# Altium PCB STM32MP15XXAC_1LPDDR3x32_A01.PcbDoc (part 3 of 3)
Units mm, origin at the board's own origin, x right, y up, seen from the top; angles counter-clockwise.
Board outline 89 x 120 mm, 6 copper layers (Top Layer, Signal Layer 1, Signal Layer 2, Signal Layer 3, Signal Layer 4, Bottom Layer), stack 1.556 mm thick; 93 components, 99 nets, 917 pads, 464 vias.
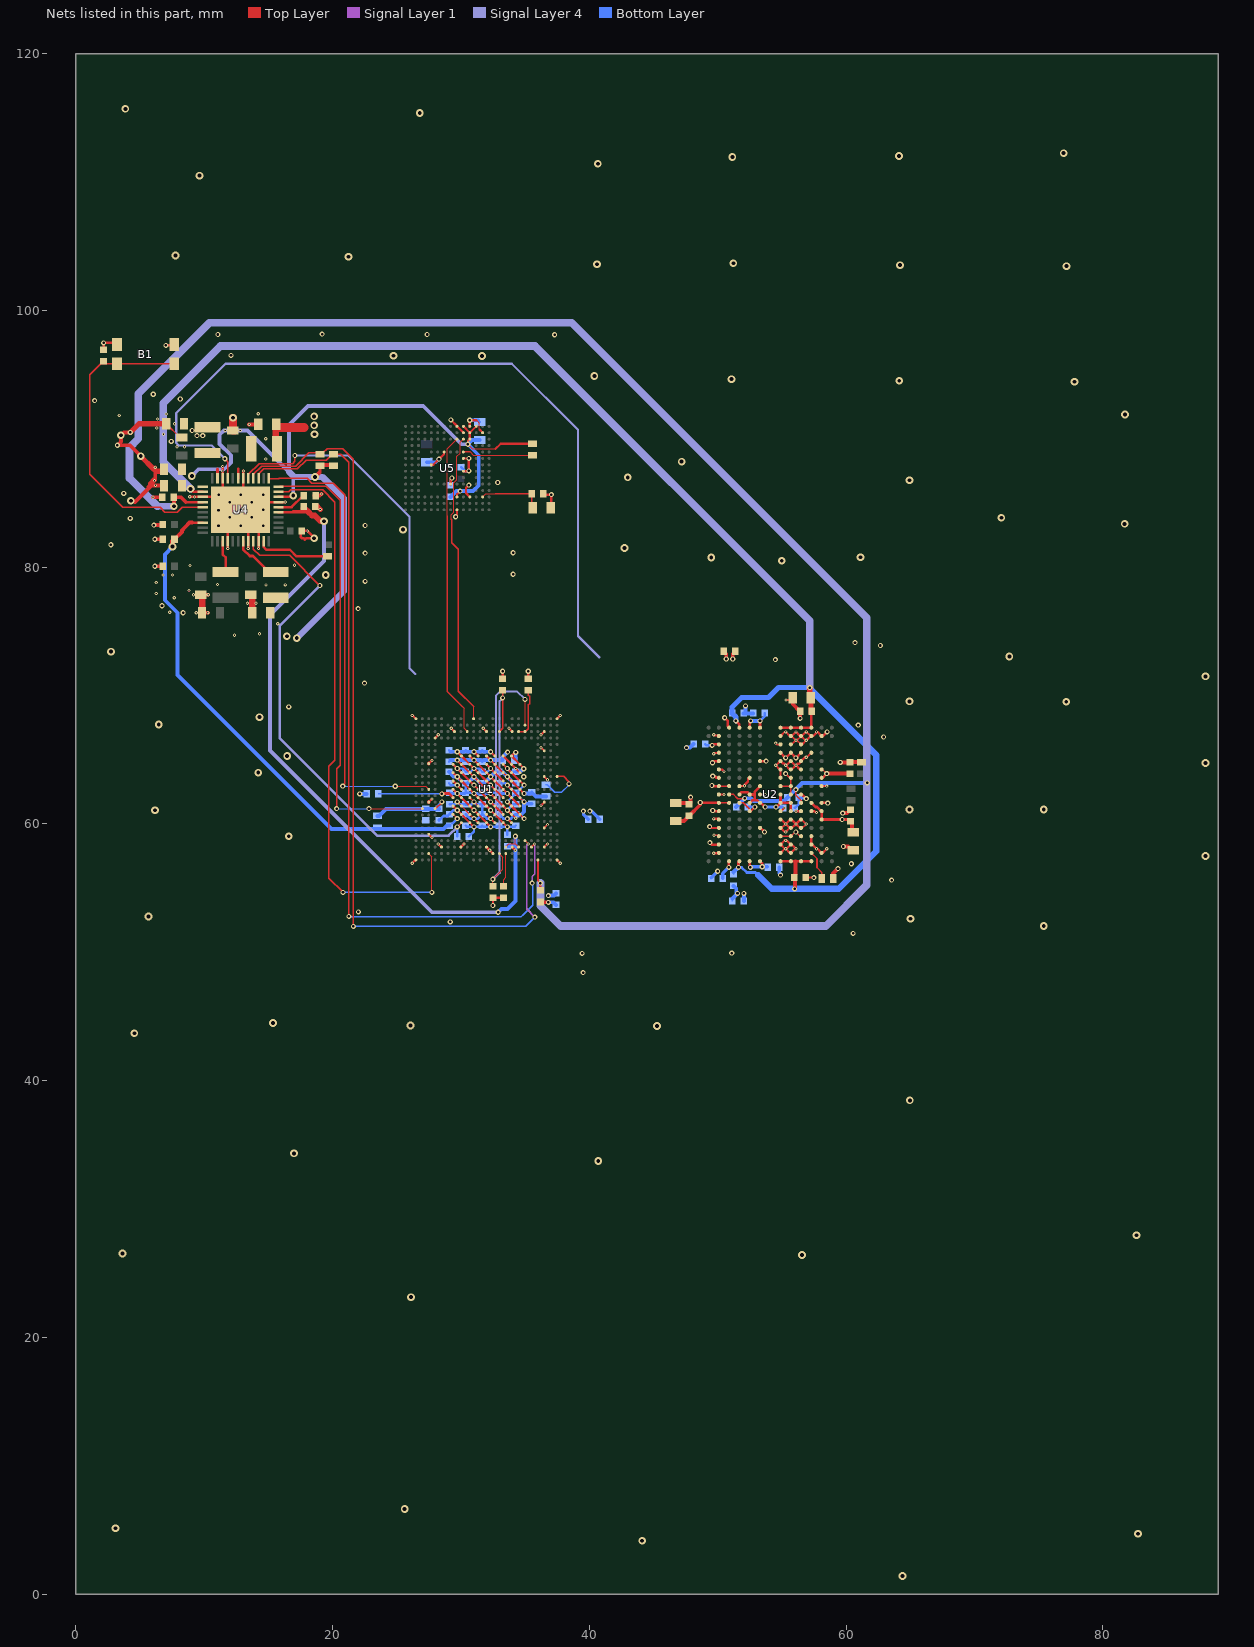
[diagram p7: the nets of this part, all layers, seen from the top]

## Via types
v1: diameter 0.4, hole 0.2, Top Layer to Bottom Layer, tented both sides, 258 vias
v2: diameter 0.25, hole 0.1, Top Layer to Signal Layer 1, tented top, 105 vias
v3: diameter 0.6, hole 0.3, Top Layer to Bottom Layer, tented both sides, 95 vias
v4: diameter 0.25, hole 0.1, Top Layer to Signal Layer 1, tented both sides, 6 vias

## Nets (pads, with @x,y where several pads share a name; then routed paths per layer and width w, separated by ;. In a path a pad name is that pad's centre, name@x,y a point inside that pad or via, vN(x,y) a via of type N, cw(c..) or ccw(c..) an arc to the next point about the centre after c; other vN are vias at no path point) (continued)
GND: B1.1 B1.2 C1.2 C2.2 C3.2 C4.2 C5.2 C6.2 C7.2 C8.2 C9.2 C10.2 C11.2 C12.2 C13.2 C14.1 C15.1 C16.1 C17.2 C18.1 C19.2 C20.2 C21.2 C29.1 C30.1 C31.1 C32.1 C33.1 C34.1 C35.1 C36.1 C37.1 C38.1 C39.1 C40.1 C41.1 C42.1 C43.2 C44.1 C45.1 C46.1 C47.1 C48.1 C49.1 C50.1 C51.1 C52.1 C53.1 C54.1 C55.1 C56.1 C57.1 C58.1 C59.1 C61.1 C66.1 C67.1 C68.1 C69.1 C70.1 C71.1 C75.1 C76.1 C77.1 C78.1 C79.1 C80.1 C81.1 C82.1 C83.1 C84.1 C92.1 C94.1 C95.1 C96.1 C149.2 C150.2 R24.2 R49.1 R65.2 U1.1A3 U1.1A5 U1.1A7 U1.1B2 U1.1B4 U1.1B6 U1.1B8 U1.1C1 U1.1C3 U1.1C5 U1.1C7 U1.1C9 U1.1D2 U1.1D4 U1.1D6 U1.1D8 U1.1E1 U1.1E3 U1.1E5 U1.1E7 U1.1E9 U1.1F2 U1.1F4 U1.1F6 U1.1F8 U1.1G1 U1.1G3 U1.1G5 U1.1G7 U1.1G9 U1.1H2 U1.1H4 U1.1H6 U1.1H8 U1.1J3 U1.1J5 U1.1J7 U1.A1 U1.A23 U1.AA5 U1.AA8 U1.AA12 U1.AA16 U1.AA21 U1.AB13 U1.AC1 U1.AC23 U1.C7 U1.C12 U1.C16 U1.C21 U1.D4 U1.F21 U1.H3 U1.K21 U1.P3 U1.P21 U1.V21 U1.W3 U2.B2 U2.B5 U2.B6 U2.B12 U2.C3 U2.C5 U2.C6 U2.D3 U2.D12 U2.E4 U2.E5 U2.E6 U2.F4 U2.F5 U2.F6 U2.F12 U2.G3 U2.G4 U2.G6 U2.G9 U2.H2 U2.H10 U2.J4 U2.J8 U2.J12 U2.K2 U2.K10 U2.L6 U2.L9 U2.M4 U2.M5 U2.M6 U2.M12 U2.N4 U2.N5 U2.N6 U2.P3 U2.P12 U2.R4 U2.R5 U2.R6 U2.T2 U2.T3 U2.T4 U2.T5 U2.T6 U2.T12 U4.6 U4.10 U4.15 U4.26 U4.30 U4.32 U4.41 U4.ep U5.A6 U5.C4 U5.E7 U5.G5 U5.H10 U5.J5 U5.K8 U5.N2 U5.N5 U5.P4 U5.P6 | length 192.9
  Top Layer w0.09: 31.225,91.45 31.45,91.225 31.45,90.725
  Top Layer w0.1: U2.H10@51.7,61.65 52.009,61.65 52.5,61.159 U2.G9@52.5,61 ; U2.E4@56.5,59.7 56.6,59.7 v2@56.86,59.96 ; U2.F4@56.5,60.35 56.55,60.35 v2(56.9,60)
  Top Layer w0.12: U1.AA21@36.5,58.2 36.504,58.2 U1.AA21@36.545,58.2 ; U1.C21@36.5,67.185 U1.C21@36.5,67.2
  Top Layer w0.127: C29.1@7.05,91.175 8.125,90.1 C18.1@8.25,90.1
  Top Layer w0.15: v2(36.25,65.945) 36.498,65.698 U1.F21@36.5,65.696 ; U1.AA21@36.5,58.196 36.502,58.198 36.504,58.2 v2@36.75,58.446 ; U1.V21@36.5,59.696 36.502,59.698 v2@36.75,59.946 ; U1.K21@36.5,63.696 v2@36.735,63.461 ; C7.2@47.675,61.625 C7.2@47.775,61.525 C7.2@47.9,61.65 ; v2(49.7,65.475) 49.75,65.525 50.1,65.525 U2.P12@50.1,65.55 ; v2(49.725,59.125) 50.025,59.125 U2.D12@50.1,59.05 ; v2(54.525,66.3) 54.65,66.175 54.875,66.175 U2.R6@54.9,66.2 ; U2.R5@55.7,66.2 55.775,66.2 v2(56.1,66.525) ; U2.T5@55.7,66.85 55.775,66.85 v2(56.1,66.525) ; U2.R4@56.5,66.2 v2@56.175,66.525 ; U2.T4@56.5,66.85 v2@56.175,66.525 ; v2(56.1,66.525) v2@56.175,66.525
  Top Layer w0.175: v2(26.225,56.95) 26.475,57.2 U1.AC1@26.5,57.2 ; v2(26.225,68.45) 26.25,68.45 U1.A1@26.5,68.2 ; U1.W3@27.5,59.2 v2(27.75,58.95) ; U1.P3@27.5,61.7 v2(27.75,61.95) ; U5.H10@27.7,87.975 27.85,87.975 v1(28.3,88.425) 28.7,88.825 U5.K8@28.7,88.975 ; U1.D4@28,66.7 v2(28.25,66.95) ; v2(28.25,58.45) U1.AA5@28.5,58.2 ; v1(29.225,91.475) 29.7,91 U5.P6@29.7,90.975 U5.N5@30.2,90.475 ; v2(29.25,67.45) U1.C7@29.5,67.2 ; U1.1G1@29.4,61.4 v1(29.725,61.075) U1.1H2@30.05,60.75 U1.1J3@30.7,60.1 v1(31.025,59.775) ; U1.1E1@29.4,62.7 v1(29.725,62.375) U1.1F2@30.05,62.05 U1.1G3@30.7,61.4 v1(31.025,61.075) U1.1H4@31.35,60.75 U1.1J5@32,60.1 v1(32.325,59.775) ; U1.1C1@29.4,64 v1(29.725,63.675) U1.1D2@30.05,63.35 U1.1E3@30.7,62.7 v1(31.025,62.375) U1.1F4@31.35,62.05 U1.1G5@32,61.4 v1(32.325,61.075) U1.1H6@32.65,60.75 U1.1J7@33.3,60.1 v1(33.625,59.775) ; v1(29.6,83.925) 29.7,84.025 U5.A6@29.7,84.475 ; v1(29.725,64.975) U1.1B2@30.05,64.65 U1.1C3@30.7,64 v1(31.025,63.675) U1.1D4@31.35,63.35 U1.1E5@32,62.7 v1(32.325,62.375) U1.1F6@32.65,62.05 U1.1G7@33.3,61.4 v1(33.625,61.075) U1.1H8@33.95,60.75 33.975,60.75 v2(34.275,60.45) ; U5.G5@30.2,87.475 30.601,87.475 v1(30.625,87.5) v1(30.625,88.475) U5.J5@30.2,88.475 ; v1(30.625,86.4) 30.4,86.175 30.4,85.775 U5.C4@30.7,85.475 ; U1.1A3@30.7,65.3 v1(31.025,64.975) U1.1B4@31.35,64.65 U1.1C5@32,64 v1(32.325,63.675) U1.1D6@32.65,63.35 U1.1E7@33.3,62.7 v1(33.625,62.375) U1.1F8@33.95,62.05 U1.1G9@34.6,61.4 ; U5.P4@30.7,90.948 U5.P4@30.7,90.975 v1(30.7,91.45) 31.225,91.45 ; 31.45,90.725 U5.N2@31.7,90.475 ; v2(31.75,67.45) U1.C12@32,67.2 ; U1.1A5@32,65.3 v1(32.325,64.975) U1.1B6@32.65,64.65 U1.1C7@33.3,64 v1(33.625,63.675) U1.1D8@33.95,63.35 U1.1E9@34.6,62.7 v1(34.925,62.375) ; v1(32.5,53.65) C67.1@32.5,54.25 C69.1@33.325,54.25 ; U1.1A7@33.3,65.3 U1.1B8@33.95,64.65 v2(34.275,64.325) U1.1C9@34.6,64 ; v2(33.75,67.45) U1.C16@34,67.2 ; U1.1C9@34.6,63.975 U1.1C9@34.6,64 ; U1.1C9@34.625,64 U1.1C9@34.6,64 ; v2(36.25,61.45) U1.P21@36.5,61.7 ; v2(36.25,66.95) U1.C21@36.5,67.2 ; C82.1@36.425,85.725 36.5,85.65 v1(37.05,85.65) 37.05,84.675 C83.1@37,84.625 ; U1.AC23@37.5,57.2 v2(37.75,56.95) ; U1.A23@37.5,68.2 v2(37.75,68.45) ; v2(49.7,57.725) 50.075,57.725 U2.B12@50.1,57.75 ; v2(49.7,60.4) 50.05,60.4 U2.F12@50.075,60.375 ; v2(49.7,66.95) 49.766,66.884 50.066,66.884 U2.T12@50.1,66.85 ; U2.J12@50.1,62.3 v4(50.5,62.3) ; U2.M12@50.1,64.25 50.35,64.25 v2(50.5,64.1) ; U2.K10@51.7,62.95 52.075,62.95 v2(52.1,62.975) 52.1,63.041 52.373,63.314 52.373,63.525 52.447,63.6 U2.L9@52.5,63.6 ; U2.G9@52.5,61 52.575,61 v1(52.9,61.325) ; U2.J8@53.3,62.3 v2(53.7,62.3) ; U2.E6@54.825,59.7 U2.E6@54.9,59.7 ; U2.B6@54.9,57.75 v2@55.225,58.075 ; U2.F6@54.9,60.35 54.95,60.35 v2(55.3,60) ; U2.G6@54.9,61.025 U2.G6@54.9,61 54.95,61 v2(55.2,61.25) ; U2.L6@54.9,63.6 U2.M6@54.9,64.25 54.85,64.25 v2(54.525,64.575) 54.575,64.575 U2.N6@54.9,64.9 54.911,64.9 55.098,64.713 55.163,64.713 v2(55.3,64.575) 55.625,64.25 U2.M5@55.7,64.25 55.775,64.25 v2(56.1,64.575) ; U2.T6@54.9,66.85 55.225,67.175 v2(55.3,67.175) 55.625,66.85 U2.T5@55.7,66.85 ; v2(55.325,69.65) 55.85,69.65 C16.1@55.875,69.675 ; v2@55.375,64.575 U2.N5@55.7,64.9 56.025,64.575 v2(56.1,64.575) ; U2.T5@55.775,66.85 v2(56.1,67.175) 56.425,66.85 U2.T4@56.5,66.85 ; v2(56.1,61) U2.G4@56.5,61 ; U2.E4@56.5,59.7 56.4,59.7 v2(56.1,60) ; U2.F4@56.5,60.35 56.45,60.35 v2(56.1,60) ; U2.J4@56.5,62.3 56.575,62.3 v1(56.9,61.975) ; U2.M4@56.5,64.25 56.425,64.25 v2(56.1,64.575) ; U2.N4@56.5,64.9 56.8,65.2 v2(56.9,65.2) 56.95,65.2 U2.P3@57.3,65.55 ; U2.R4@56.5,66.2 U2.R4@56.575,66.2 ; U2.N4@56.52,64.88 56.339,64.7 56.225,64.7 v2(56.1,64.575) ; U2.R4@56.6,66.2 U2.R4@56.575,66.2 ; C3.2@56.875,55.825 v1(57.5,55.825) ; U2.D3@57.3,59.05 U2.C3@57.3,58.4 57.375,58.4 v2(57.7,58.075) 57.775,58.075 U2.B2@58.1,57.75 58.175,57.75 v2(58.5,58.075) ; U2.G3@57.3,61 57.543,61 57.606,60.938 57.663,60.938 v2(57.7,60.9) ; v2(57.7,67.175) v2@57.775,67.175 ; U2.H2@58.1,61.65 v1@58.575,61.65 ; U2.K2@58.1,62.95 v2(58.5,62.95) ; v1(58.525,67.175) 58.2,66.85 U2.T2@58.1,66.85 v2@57.775,67.175 ; C6.2@60.1,64.8 60.125,64.825 C6.2@60.3,64.825 ; C5.2@60.25,61.075 C5.2@60.275,61.1 ; U2.E6@54.9,59.7 55.225,59.375 v2(55.3,59.375) U2.E5@55.625,59.7 ; U2.E6@54.9,59.7 55,59.7 v2(55.3,60) ; v2@55.225,58.075 v2(55.3,58.075) ; v2@55.225,58.075 U2.C6@54.9,58.4 55.225,58.725 v2(55.3,58.725) 55.375,58.725 U2.C5@55.7,58.4 ; v2(55.3,58.075) 55.375,58.075 U2.C5@55.7,58.4 ; v2(55.3,58.075) 55.625,57.75 U2.B5@55.7,57.75 56.025,58.075 v2(56.1,58.075) 55.775,58.4 U2.C5@55.7,58.4 ; v2(55.3,60) 55.65,60.35 U2.F5@55.7,60.35 55.75,60.35 v2(56.1,60) ; v2(55.3,60) 55.6,59.7 U2.E5@55.625,59.7 ; U2.E5@55.625,59.7 U2.E5@55.7,59.7 55.8,59.7 v2(56.1,60) ; U2.T4@56.5,66.85 56.55,66.85 56.888,67.188 56.9,67.2 56.912,67.188 U2.T3@57.25,66.85 ; U2.T4@56.5,66.85 v2@56.825,66.525 ; U2.R4@56.575,66.2 v2@56.862,66.488 ; v2@56.825,66.525 v2@56.862,66.488 ; v2@56.825,66.525 v2(56.9,66.525) v2@56.862,66.488 ; v2@56.862,66.488 56.875,66.475 56.913,66.513 U2.T3@57.25,66.85 ; U2.T3@57.25,66.85 U2.T3@57.3,66.85 57.45,66.85 57.737,67.138 v2@57.775,67.175
  Top Layer w0.2: C44.1@2.175,96.95 v1(2.175,97.475) 3.1,97.475 B1.1@3.225,97.35 ; v1(7.025,97.275) 7.6,97.275 B1.2@7.675,97.35 ; v4(8.882,85.482) 9.243,85.482 v4(9.25,85.475) U4.15@9.9,85.475 10.875,85.475 U4.ep@10.9,85.45 ; v2@11.45,87.825 v2(11.45,87.5) U4.10@11.45,86.925 11.45,85.875 12.125,85.2 v1(12.85,84.475) ; v2(11.85,81.45) U4.26@11.85,82.025 11.85,83.475 12.125,83.75 v1(12.85,84.475) ; v3(12.255,91.64) v3@12.381,91.514 ; v2@13.05,87.5 U4.6@13.05,86.925 13.05,85.65 U4.ep@13.05,84.675 ; v2@13.45,81.425 v2(13.45,81.45) U4.30@13.45,82.025 U4.ep@13.45,83.875 ; v2(14.25,81.45) U4.32@14.25,82.025 14.25,83.075 13.587,83.738 U4.ep@13.45,83.875 ; v2(16.325,85.075) U4.41@15.8,85.075 v1(13.725,85.075) 13.45,85.075 U4.ep@13.05,84.675 ; C51.1@17.537,82.762 17.537,82.338 17.625,82.25 17.757,82.25 17.857,82.15 17.957,82.25 v3(18.575,82.25) ; C51.1@17.6,82.825 v2(18.05,82.825) v3@18.6,82.275 ; U1.H3@27.5,64.7 v2(27.75,64.95) ; U5.E7@29.2,86.475 29.2,86.825 29.312,86.937 v1@29.325,86.95 ; U1.AA8@30,58.2 v2(30.25,58.45) ; U1.AA12@32,58.2 v2(32.25,57.95) U1.AB13@32.5,57.7 ; C66.1@33.25,71.3 v1(33.25,71.9) ; U1.AA16@34,58.2 v2(34.25,57.95) ; C68.1@35.25,71.3 v1(35.25,71.9) ; v1(12.85,84.475) U4.ep@13.45,83.875 ; v1(12.85,84.475) U4.ep@13.05,84.675
  Top Layer w0.3: v1(4.25,90.5) 3.75,90.5 v3(3.525,90.275) 3.525,89.775 v1(3.25,89.5) 4.225,89.5 v3(5.075,88.65) ; v3(4.3,85.175) 4.525,85.175 4.625,85.075 5.675,86.125 ; v2(6.025,85.45) C84.1@6.75,85.45 ; v1(6.1,83.275) 6.75,83.275 C41.1@6.8,83.325 C41.1@6.775,83.35 ; v2(6.144,86.744) 5.925,86.525 5.925,86.5 ; v1(6.175,80.075) C32.1@6.8,80.075 ; v1(6.175,82.175) C49.1@6.8,82.175 ; v2(6.2,87.775) 6.2,87.525 6.2,86.95 ; C46.1@6.85,86.375 v2(6.214,86.375) 5.925,86.375 ; C39.1@9.75,77.85 v2(10.325,77.85) ; C40.1@9.85,76.45 v2(10.3,76.45) ; C33.1@12.255,90.701 12.25,90.696 12.227,90.673 C33.1@12.25,90.65 C33.1@12.4,90.5 ; v2@13.5,91.125 v2(13.525,91.125) 13.95,91.125 14.075,91 C34.1@14.2,90.875 ; C43.2@18.6,85.575 18.649,85.526 C43.2@18.65,85.525 ; C43.2@18.684,85.562 19.012,85.562 v2(19.15,85.7) ; C17.2@36.2,53.925 36.225,53.9 v1(36.825,53.9) ; C15.1@46.75,61.625 C7.2@47.675,61.625 ; C7.2@47.9,61.65 v1(47.9,62.1) ; v1(51.175,72.85) 51.175,73.25 C19.2@51.375,73.45 ; C16.1@55.85,69.825 55.85,69.65 55.85,69.35 C1.2@56.425,68.775 v1(56.425,68.225) ; R65.2@59,55.75 59,56.15 v1(59.375,56.525) ; v1(59.55,64.8) C6.2@60.1,64.8 ; v1(59.75,60.85) 60.1,60.85 C5.2@60.35,61.1 ; v1(59.8,58.25) 60.175,58.25 C14.1@60.475,57.95 ; C6.2@60.3,64.825 R49.1@61.025,64.825 ; 5.675,86.125 5.925,86.375 ; 5.675,86.125 5.675,86.25 5.863,86.438 ; 5.863,86.438 5.775,86.525 6.069,86.819 6.2,86.95 ; 5.863,86.438 5.925,86.375 ; 5.863,86.438 5.925,86.5 ; 5.925,86.375 5.925,86.5 ; 5.925,86.5 6.157,86.732 6.2,86.775 6.2,86.95
  Top Layer w0.4: v1(4.25,90.5) 4.925,91.175 6.325,91.175 C29.1@7.05,91.175 ; v3(5.075,88.65) 6.075,87.65 6.2,87.525 6.25,87.475 C42.1@6.6,87.475 ; C52.1@18.751,84.801 v2(19.053,84.5)
  Top Layer w0.5: C39.1@9.75,77.85 9.85,77.75 C40.1@9.85,76.45 ; C31.1@13.625,77.85 13.625,77.75 13.75,77.625 13.75,77.2 C38.1@13.75,76.45
  Top Layer w0.6: C33.1@12.25,90.65 12.25,90.696 12.25,91.635 v3(12.255,91.64)
  Bottom Layer w0.1: C13.2@51.15,54 C13.2@51.15,54.2
  Bottom Layer w0.15: C9.2@49.5,55.75 C9.2@49.5,55.825
  Bottom Layer w0.175: C35.1@29.075,64.85 C35.1@29.2,64.975 ; C37.1@30.225,63.175 C37.1@30.375,63.175 C37.1@30.525,63.175 ; C96.1@30.375,59.875 C96.1@30.475,59.775 ; C47.1@30.625,59.025 31.025,59.425 v1(31.025,59.775) ; C81.1@31.325,91.45 C81.1@31.475,91.3 ; C36.1@31.525,63.175 C36.1@31.675,63.175 C36.1@31.825,63.175 ; C76.1@31.55,64.975 C76.1@31.675,64.85 C76.1@31.8,64.975 ; C95.1@31.575,59.775 C95.1@31.675,59.875 C95.1@31.775,59.775 ; C45.1@32.725,64.075 C45.1@32.975,64.075 C45.1@33.225,64.075 ; C55.1@32.875,59.775 C55.1@32.975,59.875 C55.1@33.075,59.775 ; C53.1@33.25,65.2 33.25,64.975 C53.1@33.275,64.95 ; C57.1@34.125,63.175 C57.1@34.275,63.175 ; C54.1@34.175,59.775 C54.1@34.275,59.875 ; C59.1@35.4,62.375 35.512,62.488 C59.1@35.525,62.5 ; C4.2@52.025,68.6 52.05,68.625 C4.2@52.175,68.75 ; v1@56.85,62.025 v1(56.9,61.975)
  Bottom Layer w0.2: C58.1@28.3,60.35 C58.1@28.3,60.275 28.65,60.625 28.975,60.625 C70.1@29.125,60.775 29.425,61.075 v1(29.725,61.075) ; C94.1@29.125,62.425 29.175,62.375 v1(29.725,62.375) 30.325,62.375 C48.1@30.375,62.425 ; C80.1@29.2,86.375 29.2,86.825 29.312,86.937 v1@29.325,86.95 ; C78.1@30.025,87.8 30.35,87.475 30.6,87.475 v1(30.625,87.5) ; C37.1@30.375,63.175 C48.1@30.375,62.425 ; C96.1@30.475,59.775 v1(31.025,59.775) C95.1@31.575,59.775 ; C92.1@31.675,62.425 C92.1@31.725,62.375 ; C95.1@31.775,59.775 v1(32.325,59.775) C55.1@32.875,59.775 ; C55.1@33.075,59.775 v1(33.625,59.775) ; C71.1@33.625,59.175 v1(33.625,59.775) ; v1(33.625,61.075) 34.075,61.525 C56.1@34.275,61.525 ; v1(33.625,62.375) 33.025,62.375 C77.1@32.975,62.425 32.375,62.425 v1(32.325,62.375) C92.1@31.725,62.375 ; C54.1@34.175,59.775 v1(33.625,59.775) ; C150.2@52.325,61.325 C150.2@52.35,61.325 v1(52.9,61.325) ; C8.2@56.025,61.25 56.325,61.55 56.325,62.025 v1@56.85,62.025 ; C48.1@30.375,62.425 30.975,62.425 v1(31.025,62.375) 31.675,62.375 C92.1@31.725,62.375
  Bottom Layer w0.25: v1(39.55,61) 39.55,60.75 C21.2@39.925,60.375 ; C9.2@49.5,55.825 v1(50,56.325)
  Bottom Layer w0.3: v1(22.125,62.35) C61.1@22.675,62.35 ; C79.1@27.35,88.175 28.05,88.175 v1(28.3,88.425) ; C75.1@29.075,64.075 29.475,63.675 v1(29.725,63.675) C37.1@30.225,63.175 ; C35.1@29.2,64.975 v1(29.725,64.975) 30.375,64.975 v1(31.025,64.975) C76.1@31.55,64.975 ; C37.1@30.525,63.175 v1(31.025,63.675) C36.1@31.525,63.175 ; v1(30.7,91.45) C81.1@31.325,91.45 ; C76.1@31.8,64.975 v1(32.325,64.975) C53.1@33.25,64.975 ; C36.1@31.825,63.175 v1(32.325,63.675) C45.1@32.725,64.075 ; C45.1@33.225,64.075 v1(33.625,63.675) C57.1@34.125,63.175 ; C53.1@33.25,65.2 v1(33.65,65.6) ; v1(34.925,62.375) 35.4,62.375 35.425,62.375 C59.1@35.525,62.475 35.85,62.15 R24.2@36.625,62.15 ; v1(36.825,53.9) 37.225,53.9 C20.2@37.425,53.7 ; v1(47.575,65.95) 47.85,65.95 C12.2@48.125,66.225 ; C13.2@51.15,54.2 v1(51.55,54.6) ; C2.2@51.25,55.175 51.45,54.975 v1@51.45,54.6 ; C4.2@52.025,68.6 C10.2@52.775,68.6 ; C4.2@52.175,68.75 v1(52.175,69.2) ; C11.2@54.8,56.625 54.8,56.184 v1@54.93,56.055
  other v1: 39.525,48.425 39.45,49.925 51.1,49.95 60.55,51.485 29.175,52.375 22.025,53.15 63.55,55.625 54.9,56.025 60.425,56.9 58.575,61.625 34.9,63.675 62.925,66.775 60.95,67.7 16.6,69.125 22.5,70.975 54.5,72.8 62.675,73.9 60.7,74.125 8.375,76.45 22,76.775 6.725,77 22.55,78.9 34.075,79.45 22.55,81.1 34.075,81.125 2.75,81.75 11.125,83.225 12.875,83.225 14.6,83.225 22.55,83.25 4.25,83.801 12,83.875 13.725,83.875 11.125,84.45 14.6,84.475 12,85.075 11.15,85.65 12.875,85.65 14.6,85.65 3.75,85.75 32.875,86.6 29.3,86.95 7.45,89.8 1.475,92.975 8.15,93.1 6.05,93.475 12.1,96.5 37.3,98.1 11.075,98.125 27.375,98.125 19.2,98.15
  other v2: 36.75,58.45 36.75,59.95 36.75,63.45 56.9,67.175 12.375,74.7 14.325,74.825 15.75,75.6 9.4,76.45 13.375,77.2 14.05,77.2 7.675,77.625 9.175,77.85 8.825,78.175 14.825,78.625 16.325,78.625 11.05,78.65 6.8,79.4 7.55,79.4 8.911,80.125 17.05,80.15 13.075,87.5 11.45,87.85 14.8,88.425 7.9,89.375 8.475,89.375 14.8,90 6.85,90.35 11.65,90.65 12.825,90.65 6.325,90.85 7.7,91.175 6.375,91.55 3.4,91.825 7.05,91.925 14.225,91.95
  other v3: 64.4,1.425 44.125,4.175 82.75,4.725 3.1,5.15 25.625,6.65 26.125,23.15 56.575,26.425 3.65,26.55 82.625,27.975 40.7,33.75 17,34.35 64.975,38.475 4.575,43.7 45.275,44.275 26.075,44.3 15.375,44.5 75.4,52.05 65.025,52.625 5.675,52.8 88,57.5 16.6,59.05 6.175,61.075 64.95,61.125 75.4,61.125 14.225,64 88,64.75 16.475,65.3 6.475,67.75 14.325,68.325 77.15,69.525 64.95,69.55 88,71.5 72.725,73.05 2.75,73.425 19.475,79.4 55,80.5 49.5,80.75 61.125,80.775 42.75,81.5 25.5,82.925 81.7,83.375 72.1,83.85 64.95,86.775 43,87 47.2,88.225 81.725,91.9 77.8,94.45 64.15,94.525 51.075,94.65 40.4,94.9 31.65,96.45 24.75,96.475 77.175,103.45 64.2,103.525 40.6,103.6 51.225,103.675 21.25,104.175 7.775,104.275 9.65,110.5 40.675,111.425 51.15,111.95 64.125,112.025 76.95,112.25 26.8,115.375 3.875,115.7
  other v4: 7.325,76.5 6.275,77.95 6.275,78.8
I2C4_SCL: R37.2 U1.Y18 U4.4 | length 66.5
  Top Layer w0.09: U1.Y18@35,58.7 v2(35.25,58.45)
  Top Layer w0.1: U4.4@13.85,86.925 13.85,87.237 14.488,87.875 17.125,87.875 18.15,88.9 19.025,88.9 19.26,88.9 19.6,89.24 20.81,89.24 21.638,88.413 v1(21.638,52.025)
  Signal Layer 1 w0.1: v2(35.25,58.45) 35.14,58.34 35.14,53.385 v1(35.775,52.75)
  Bottom Layer w0.1: v1(21.638,52.025) 35.05,52.025 v1(35.775,52.75)
I2C4_SDA: R38.2 U1.AA19 U4.3 | length 63.6
  Top Layer w0.1: U4.3@14.25,86.925 14.25,87.267 14.658,87.675 17.275,87.675 17.95,88.35 19.525,88.35 20.012,88.838 R38.2@19.975,88.875 ; R38.2@20.074,88.813 20.637,88.813 21.288,88.162 v1(21.288,52.8) ; U1.AA19@35.5,58.2 v2(35.75,58.45)
  Signal Layer 1 w0.12: v1(35.55,55.4) 35.55,55.9 35.75,56.1 v2(35.75,58.45)
  Bottom Layer w0.1: 34.813,52.888 35.525,53.6 ; v1(35.55,55.4) 35.6,55.35 35.6,54.225
  Bottom Layer w0.12: v1(21.288,52.8) 21.323,52.765 34.69,52.765 34.813,52.888 ; 35.525,53.6 35.6,53.675 35.6,54.225
NetB1_3: B1.3 B1.4 C44.2 U4.17 | length 24.9
  Top Layer w0.1: B1.4@7.675,95.85 B1.3@3.225,95.85 2.175,95.85 1.95,95.85 1.1,95 1.1,87.25 3.675,84.675 6.575,84.675 6.95,84.3 7.925,84.3 8.3,84.675 U4.17@9.9,84.675
NetC43_1: C43.1 U4.40 | length 2.2
  Top Layer w0.2: U4.40@15.8,84.675 16.828,84.675 C43.1@17.689,85.536
NetC61_2: C61.2 U1.1F1 | length 6
  Top Layer w0.2: v1@28.55,62.375 29.075,62.375 U1.1F1@29.4,62.05
  Top Layer w0.3: v1@28.475,62.35 v1(28.525,62.35) v1@28.55,62.375
  Bottom Layer w0.1: C61.2@23.575,62.35 v1(28.525,62.35)
NetC68_2: C68.2 U1.C17 U1.C18 | length 3.9
  Top Layer w0.1: U1.C17@34.5,67.2 U1.C18@35,67.2 35.025,67.2 35.25,67.425 35.25,69.275 35.35,69.375 35.35,69.945 35.25,70.045 C68.2@35.25,70.4
NetC69_2: C69.2 U1.AB15 | length 2.6
  Top Layer w0.09: C69.2@33.325,55.15 33.325,55.675 33.5,55.85 U1.AB15@33.5,57.7
NetC82_2: C82.2 C83.2 U5.C2 | length 5.1
  Top Layer w0.09: U5.C2@31.7,85.475 31.95,85.725 32.7,85.725
  Top Layer w0.1: 32.7,85.725 C82.2@35.525,85.725 35.525,84.7 C83.2@35.6,84.625
NetL1_1: L1.1 U4.7 | length 0.7
  Top Layer w0.2: U4.7@12.65,86.925 12.65,87.672
NetL2_1: L2.1 U4.11 | length 0.7
  Top Layer w0.2: U4.11@11.05,86.925 11.05,87.65
NetL3_1: L3.1 U4.29 | length 3.9
  Top Layer w0.2: U4.29@13.05,82.025 13.05,81.39 13.565,80.875 13.8,80.875 15.05,79.625 L3.1@15.575,79.625
NetL4_1: L4.1 U4.25 | length 2.4
  Top Layer w0.2: U4.25@11.45,82.025 11.45,81 11.675,80.775 L4.1@11.675,79.725
NetR24_1: R24.1 U1.K23 | length 3.6
  Top Layer w0.1: U1.K23@37.5,63.7 38.025,63.7 38.425,63.3 v1(38.425,63.125)
  Bottom Layer w0.12: R24.1@36.625,63.05 36.725,63.05 37.31,62.465 37.849,62.465 38.425,63.041 v1(38.425,63.125)
NetR40_1: R40.1 U5.K5 | length 5.5
  Top Layer w0.09: 30.725,88.975 30.975,88.725 R40.1@35.575,88.725
  Top Layer w0.1: U5.K5@30.2,88.975 30.725,88.975
NetR43_1: R43.1 U4.33 | length 5.7
  Top Layer w0.2: U4.33@14.65,82.025 14.65,81.561 14.836,81.375 16.675,81.375 17.2,80.85 R43.1@19.625,80.85
NetR65_1: R65.1 U2.B3 | length 2.3
  Top Layer w0.12: U2.B3@57.3,57.75 57.74,57.31 57.74,56.61 58.1,56.25 R65.1@58.1,55.75
NRST: U1.M3 U4.1 | length 36
  Top Layer w0.09: v1(24.89,62.94) 27.26,62.94 U1.M3@27.5,62.7
  Top Layer w0.1: U4.1@15.05,86.875 15.82,86.875 15.87,86.925 18.025,86.925 18.4,86.55 20.075,86.55 20.975,85.65 20.975,63.125 v1(20.8,62.95)
  Bottom Layer w0.09: v1(20.8,62.95) 24.88,62.95 v1(24.89,62.94)
PA0_WKUP: U1.AB3 U4.43 | length 46
  Top Layer w0.09: U1.AB3@27.5,57.7 27.75,57.45 v1(27.75,54.675)
  Top Layer w0.1: U4.43@15.8,85.875 16.614,85.875 16.764,86.025 19.25,86.025 20.2,85.075 20.2,64.975 19.725,64.5 19.725,55.775 v1(20.825,54.675)
  Bottom Layer w0.1: v1@20.8,54.675 v1(20.825,54.675) v1(27.75,54.675)
PWR_ON: U1.R2 U4.44 | length 36.1
  Top Layer w0.09: v1@22.825,61.2 v1(22.85,61.2) U1.R2@27,61.2
  Top Layer w0.1: U4.44@15.85,86.225 15.925,86.3 19.525,86.3 20.6,85.225 20.6,64.575 20.325,64.3 v1(20.325,61.2)
  Bottom Layer w0.09: v1(20.325,61.2) v1(22.85,61.2)
SDMMC2_CK: U1.C9 U5.M6 | length 23.7
  Top Layer w0.09: 28.95,84 28.95,89.225 U5.M6@29.7,89.975 ; 30.137,69.138 30.25,69.025 30.25,67.45 U1.C9@30.5,67.2
  Top Layer w0.13: 28.95,84 28.95,70.325 30.137,69.138
SDMMC2_CMD: U1.A10 U5.M5 | length 22.9
  Top Layer w0.09: 29.255,83.745 29.255,84.068 29.46,84.273 29.46,86.574 29.7,86.814 29.7,88.636 29.95,88.886 29.95,89.725 U5.M5@30.2,89.975 ; U1.A10@31,68.2 31,69.15
  Top Layer w0.13: 29.255,83.745 29.3,83.7 29.3,81.9 29.8,81.4 29.8,70.35 31,69.15
VDD: C38.2 C42.2 C47.2 C48.2 C80.2 C81.2 C92.2 C94.2 C95.2 C96.2 L3.2 R37.1 R38.1 R40.2 U1.1F3 U1.1G2 U1.1G4 U1.1H3 U1.1H5 U1.1J2 U1.1J4 U1.1J6 U1.B18 U4.13 U4.31 U4.42 U5.C6 U5.M4 U5.N4 U5.P3 U5.P5 | length 133
  Top Layer w0.09: v1(30.55,89.575) 30.9,89.225 32.7,89.225 ; U1.B18@35,67.7 v1(35,69.7) v1@35,69.8
  Top Layer w0.1: U4.31@13.85,82.025 13.85,81.4 14.325,80.925 16.675,80.925 v1(19.025,78.575)
  Top Layer w0.12: v1(29.725,59.775) U1.1J2@30.05,60.1 ; v1(29.725,61.725) U1.1G2@30.05,61.4 U1.1H3@30.7,60.75 v1(31.025,60.425) U1.1J4@31.35,60.1 ; U1.1F3@30.7,62.05 v1(31.025,61.725) U1.1G4@31.35,61.4 ; U1.1H5@32,60.75 v1(32.325,60.425) U1.1J6@32.65,60.1
  Top Layer w0.175: U5.C6@29.7,85.475 29.7,85.675 v1(29.95,85.925) ; U5.P5@30.2,90.975 U5.N4@30.7,90.475 ; v1(30.55,89.575) 30.55,89.825 U5.M4@30.7,89.975 U5.N4@30.7,90.475 ; U5.P3@31.2,90.975 U5.N4@30.7,90.475 ; 32.7,89.225 33.1,89.625 R40.2@35.575,89.625
  Top Layer w0.2: U4.42@15.8,85.475 v3@16.85,85.475 ; v3@16.85,85.475 v3(16.95,85.575) ; v3@16.85,85.475 v3(16.95,85.575) ; v3(16.95,85.575) v3(16.95,85.575) 16.95,85.579 v3(16.95,85.575)
  Top Layer w0.25: 19,87.375 19.025,87.4 R37.1@19.025,87.9
  Top Layer w0.3: v3@18.65,87.15 v3(18.65,87.025) 19,87.375 ; R37.1@19.325,87.95 20.074,87.95 R38.1@20.175,87.95
  Signal Layer 4 w0.15: 32.6,60.675 32.725,60.8 32.725,69.975 33.075,70.325 34.375,70.325 v1(35,69.7)
  Signal Layer 4 w0.2: 16.95,87.1 17.025,87.025 ; v1(19.025,78.575) 15.9,75.45 15.9,66.675 23.475,59.1 29.05,59.1 v1(29.725,59.775)
  Signal Layer 4 w0.3: v3(9.05,87.1) 9.575,87.625 11.575,87.625 12.1,88.15 12.1,88.725 11.217,89.608 11.217,90.317 11.55,90.65 13.4,90.65 16.625,87.425 16.625,91.075 18.1,92.55 27.075,92.55 30.05,89.575 v1(30.55,89.575) ; v3(16.95,85.575) 16.95,87.1
  Signal Layer 4 w0.5: 16.625,87.425 16.95,87.1 ; 17.025,87.025 v3(18.65,87.025) 19.225,87.025 20.875,85.375 20.875,78.125 v3(17.225,74.475)
  Bottom Layer w0.175: C47.2@29.725,59.025 v1(29.725,59.775)
  Bottom Layer w0.2: C94.2@29.125,61.525 29.525,61.525 v1(29.725,61.725) 29.925,61.525 C48.2@30.375,61.525 ; C96.2@30.375,60.775 30.725,60.425 v1(31.025,60.425) 31.325,60.425 C95.2@31.675,60.775 ; C48.2@30.4,61.5 30.8,61.5 v1(31.025,61.725) 31.225,61.525 C92.2@31.675,61.525 C95.2@31.675,60.775 ; v1(32.325,60.425) 32.025,60.425 C95.2@31.675,60.775
  Bottom Layer w0.3: C80.2@29.2,85.475 29.65,85.925 v1(29.95,85.925) 30.95,85.925 31.4,86.375 31.4,88.725 v1(30.55,89.575) 30.875,89.9 C81.2@31.475,89.9
  other v3: 16.45,74.625
VDD1_DDR: C1.1 C2.1 C3.1 C4.1 C16.2 C46.2 U2.A3 U2.A4 U2.A5 U2.A6 U2.A10 U2.U3 U2.U4 U2.U5 U2.U6 U2.U10 U4.14 | length 121.5
  Top Layer w0.12: C1.1@57.275,68.65 57.325,68.6 C1.1@57.3,68.575
  Top Layer w0.2: 9.175,85.875 U4.14@9.9,85.875 ; v1(51.425,68.025) 51.7,67.75 U2.U10@51.7,67.5 ; v1(51.625,56.625) 51.625,57.025 U2.A10@51.7,57.1 ; U2.A6@54.9,57.1 U2.A5@55.7,57.1 56.075,57.1 U2.A4@56.5,57.1 U2.A3@57.28,57.1 ; U2.U6@54.9,67.5 U2.U5@55.7,67.5 U2.U4@56.5,67.5 U2.U3@57.3,67.5 C1.1@57.3,68.575
  Top Layer w0.3: C3.1@56,56.025 56.075,56.1 56.075,57.1 ; v1@56.025,54.95 C3.1@56.025,55.75
  Top Layer w0.4: v1(57.175,70.625) 57.175,69.9 C16.2@57.25,69.825 ; C1.1@57.275,68.65 57.275,68.775 57.275,69.65 C16.2@57.3,69.65
  Signal Layer 4 w0.6: v3(8.95,86.1) 6.825,88.225 6.825,92.775 11.275,97.225 35.775,97.225 57.175,75.825 v1(57.175,70.625)
  Bottom Layer w0.12: C2.1@51.25,56.075 C2.1@51.25,56.25
  Bottom Layer w0.2: v1(51.625,56.625) 51.875,56.625 52.275,56.225 52.95,56.225 53.175,56
  Bottom Layer w0.3: C2.1@51.25,56.25 v1(51.625,56.625)
  Bottom Layer w0.4: C4.1@51.125,68.6 C4.1@51.125,68.65 51.125,69.1 51.875,69.85 53.965,69.85 54.74,70.625 v1(57.175,70.625) ; C4.1@51.125,68.625 51.425,68.325 v1(51.425,68.025)
  Bottom Layer w0.5: 53.175,56 54.225,54.95 v1(56,54.95) ; v1@56.025,54.95 59.425,54.95 62.35,57.875 62.35,65.375 v1@57.138,70.588
VDD2_DDR: C5.1 C6.1 C7.1 C8.1 C9.1 C10.1 C11.1 C12.1 C13.1 C14.2 C15.2 C19.1 C20.1 C21.1 C29.2 C45.2 C53.2 C54.2 C55.2 C56.2 C57.2 C59.2 L2.2 U1.1A8 U1.1B7 U1.1B9 U1.1C8 U1.1D9 U1.1E8 U1.1F9 U1.1G8 U1.1H9 U1.1J8 U2.A8 U2.A9 U2.A11 U2.C12 U2.D4 U2.D5 U2.D6 U2.E8 U2.E12 U2.F2 U2.G2 U2.G5 U2.G12 U2.H3 U2.H5 U2.H6 U2.H8 U2.H9 U2.H11 U2.H12 U2.J5 U2.J6 U2.J9 U2.J10 U2.K5 U2.K6 U2.K8 U2.K11 U2.K12 U2.L2 U2.L5 U2.L12 U2.M2 U2.N8 U2.N12 U2.P4 U2.P5 U2.P6 U2.R12 U2.U8 U2.U9 U2.U11 U4.9 | length 125.2
  Top Layer w0.1: v1(11.625,88.45) 11.85,88.225 U4.9@11.85,86.925 ; v1(49.375,59.8) v1@49.475,59.7
  Top Layer w0.12: U2.H12@50.1,61.65 U2.H11@50.9,61.65 ; U2.K12@50.1,62.95 U2.K11@50.9,62.95 ; U2.E8@53.225,59.7 U2.E8@53.3,59.7 ; U2.D6@54.9,59.05 U2.D5@55.7,59.05 56.025,59.375 v1(56.1,59.375) 56.425,59.05 U2.D4@56.5,59.05 ; U2.K6@54.9,62.95 U2.K5@55.7,62.95 ; U2.P6@54.9,65.55 U2.P6@54.961,65.55 ; v1(55.3,63.925) 55.625,63.6 U2.L5@55.7,63.6 U2.K5@55.7,62.95 ; U2.J5@55.7,62.3 U2.K5@55.7,62.95 ; U2.P5@55.7,65.55 U2.P5@55.775,65.55 ; U2.L2@58.1,63.6 U2.L2@58.175,63.6 ; U2.M2@58.1,64.25 58.175,64.25 v1(58.5,63.925)
  Top Layer w0.15: U1.1H9@34.6,60.75 v1(34.925,60.425) ; U1.1F9@34.6,62.05 v1(34.925,61.725) ; U1.1D9@34.6,63.35 v1(34.925,63.025) ; v1@49.475,59.7 U2.E12@50.1,59.7
  Top Layer w0.175: U1.1B7@33.3,64.65 v1(33.625,64.325) U1.1C8@33.95,64 U1.1D9@34.6,63.35 ; v1(33.625,60.425) U1.1J8@33.95,60.1 ; v1(33.625,61.725) U1.1G8@33.95,61.4 U1.1H9@34.6,60.75 ; v1(33.625,63.025) U1.1E8@33.95,62.7 U1.1F9@34.6,62.05 ; v1(34.275,65.575) 34.225,65.575 U1.1A8@33.95,65.3 U1.1B9@34.6,64.65 ; U1.1B9@34.6,64.625 U1.1B9@34.6,64.65 ; v1@34.9,64.35 U1.1B9@34.6,64.65
  Top Layer w0.2: v1@48.63,61.65 v1@48.645,61.65 ; v1@48.645,61.495 v1@48.645,61.65 ; v1(49.4,58.55) 49.55,58.4 U2.C12@50.1,58.4 ; v1(49.55,63) 49.6,62.95 U2.K12@50.1,62.95 ; v1(49.575,66.125) 49.65,66.2 U2.R12@50.1,66.2 ; v1(49.6,64.775) 49.725,64.9 U2.N12@50.1,64.9 ; v1(49.625,61.05) 49.675,61 U2.G12@50.1,61 ; v1(49.625,63.725) 49.675,63.675 49.854,63.675 49.929,63.6 U2.L12@50.1,63.6 ; U2.H12@50.1,61.65 v1@48.645,61.65 ; v1(50.55,68.275) 50.775,68.05 50.775,67.625 U2.U11@50.9,67.5 ; v1(50.875,56.625) 50.875,57.075 U2.A11@50.9,57.1 ; U2.J10@51.7,62.3 51.875,62.475 52.325,62.475 U2.J9@52.5,62.3 52.875,62.3 52.9,62.275 ; U2.A9@52.5,57.1 52.5,56.675 v1(52.55,56.625) ; U2.H9@52.5,61.65 52.7,61.85 52.9,61.85 ; U2.U9@52.5,67.5 52.5,67.95 v1(52.575,68.025) ; U2.A8@53.3,57.1 53.475,56.925 v1(53.475,56.675) ; U2.K8@53.3,62.95 53.3,62.925 52.9,62.525 52.9,62.275 ; U2.N8@53.3,64.9 v1(53.775,64.9) ; U2.U8@53.3,67.5 v1(53.3,68.025) ; U2.E8@53.357,59.7 v1@53.654,59.404 ; v1(53.7,61.325) 53.375,61.65 U2.H8@53.3,61.65 53.1,61.85 52.9,61.85 ; v1(54.55,61.325) 54.575,61.325 U2.H6@54.9,61.65 ; U2.J6@54.9,62.3 U2.H6@54.9,61.65 ; U2.P6@54.9,65.55 v1(55.3,65.15) U2.P5@55.7,65.55 v1(56.1,65.15) U2.P4@56.5,65.55 ; U2.G5@55.7,61 U2.H5@55.7,61.65 U2.H6@54.9,61.65 ; U2.H3@57.3,61.65 57.625,61.325 57.735,61.325 U2.G2@58.025,61.035 ; U2.G2@58.1,61 U2.F2@58.1,60.35 v1(59.7,60.35) 60.125,60.35 60.313,60.163 C5.1@60.475,60 ; U2.L2@58.175,63.6 v1(58.5,63.925) ; 52.9,61.85 52.9,62.275
  Top Layer w0.3: C15.2@46.75,60.225 47.375,60.225 C7.1@47.775,60.625 v1@48.645,61.495 ; v1@48.645,61.65 v1(48.645,61.675) ; C19.1@50.475,73.45 50.675,73.25 v1(50.675,72.85) ; v1(58.5,63.925) C6.1@60.3,63.925 ; C14.2@60.475,59.35 C5.1@60.475,60
  Signal Layer 4 w0.175: v1@11.7,88.45 v1(11.625,88.45) 10.6,89.475 8.037,89.475 7.838,89.675 7.838,92.012 11.675,95.85 33.975,95.85 39.125,90.7 39.125,74.65 40.8,72.975
  Bottom Layer w0.127: 34.7,60.65 34.7,60.725
  Bottom Layer w0.175: C45.2@32.975,63.175 33.475,63.175 v1(33.625,63.025) 33.898,62.752 33.973,62.752 34.275,62.45 C56.2@34.275,62.425 ; v1(33.625,61.725) C56.2@34.275,62.375 ; v1(33.625,64.325) 33.875,64.075 C57.2@34.275,64.075 ; C54.2@34.275,60.775 C54.2@34.325,60.725 ; C53.2@34.275,65.05 C53.2@34.296,65.004 ; v1@34.9,63 34.325,62.425 C56.2@34.275,62.425 ; v1(34.925,61.725) C56.2@34.275,62.375 ; C56.2@34.275,62.375 C56.2@34.275,62.425
  Bottom Layer w0.2: C55.2@32.975,60.775 33.325,60.425 v1(33.625,60.425) 33.925,60.425 C54.2@34.275,60.775 ; 34.7,60.65 v1(34.925,60.425) ; C12.1@49.025,66.225 49.125,66.125 v1(49.575,66.125) ; v1(53.3,68.025) 53.675,68.4 C10.1@53.675,68.625 ; v1(53.7,61.325) v1(54.55,61.325) 55.05,61.325 C8.1@55.125,61.25
  Bottom Layer w0.25: v1(40.05,61) 40.2,61 C21.1@40.825,60.375 ; C9.1@50.4,55.75 50.4,56.15 v1(50.875,56.625)
  Bottom Layer w0.3: C57.2@34.275,64.075 34.65,64.075 v1@34.887,64.312 ; C53.2@34.275,65.05 v1(34.275,65.575) ; C54.2@34.325,60.725 34.7,60.725 34.925,60.95 v1(34.925,61.725) ; v1@34.925,61.75 34.937,61.738 35.1,61.575 C59.2@35.525,61.575 ; v1(36.825,54.425) 37.25,54.425 C20.1@37.425,54.6 ; C13.1@52.05,54 v1(52.05,54.6) ; v1@52.55,56.575 52.575,56.6 52.65,56.675 v1(53.475,56.675) C11.1@53.85,56.675 ; v1(52.575,68.025) v1(53.3,68.025)
  other v1: 53.65,59.375 34.9,64.3 9.45,90.25 9.9,90.25 9.075,90.65
VDD_CORE: C30.2 C34.2 C35.2 C36.2 C37.2 C75.2 C76.2 C77.2 L1.2 U1.1A2 U1.1A4 U1.1A6 U1.1B1 U1.1B3 U1.1B5 U1.1C2 U1.1C4 U1.1C6 U1.1D1 U1.1D3 U1.1D5 U1.1D7 U1.1E2 U1.1E4 U1.1E6 U1.1F5 U1.1F7 U1.1G6 U1.1H7 U4.5 | length 54.1
  Top Layer w0.1: U4.5@13.45,86.925 13.45,87.237 14.288,88.075 16.9,88.075 17.075,88.25 v1(17.075,88.7)
  Top Layer w0.175: U1.1D1@29.4,63.35 v1(29.725,63.025) U1.1E2@30.05,62.7 ; U1.1B1@29.4,64.65 v1(29.725,64.325) U1.1C2@30.05,64 U1.1D3@30.7,63.35 v1(31.025,63.025) U1.1E4@31.35,62.7 U1.1F5@32,62.05 v1(32.325,61.725) U1.1G6@32.65,61.4 U1.1H7@33.3,60.75 ; v1(29.725,65.625) U1.1A2@30.05,65.3 U1.1B3@30.7,64.65 v1(31.025,64.325) U1.1C4@31.35,64 U1.1D5@32,63.35 v1(32.325,63.025) U1.1E6@32.65,62.7 U1.1F7@33.3,62.05 ; v1(31.025,65.625) U1.1A4@31.35,65.3 ; U1.1B5@32,64.65 v1(32.325,64.325) U1.1C6@32.65,64 U1.1D7@33.3,63.35 ; v1(32.325,65.625) U1.1A6@32.65,65.3
  Top Layer w0.5: C34.2@15.6,90.875 15.6,89.3 L1.2@15.675,89.225
  Top Layer w0.7: C34.2@15.675,90.875 17.775,90.875
  Signal Layer 4 w0.175: v1(17.075,88.7) 21.225,88.7 26,83.925 26,72.125 26.45,71.675
  Bottom Layer w0.175: C75.2@29.075,63.175 29.225,63.025 v1(29.725,63.025) ; C35.2@29.075,65.75 C35.2@29.2,65.625 ; v1(29.725,64.325) 30.125,64.325 C37.2@30.375,64.075 30.775,64.075 v1(31.025,64.325) 31.425,64.325 C36.2@31.675,64.075 32.075,64.075 v1(32.325,64.325) ; C30.2@30.25,65.625 C30.2@30.375,65.75 C30.2@30.5,65.625 ; C76.2@31.55,65.625 C76.2@31.675,65.75 C76.2@31.8,65.625
  Bottom Layer w0.2: v1(32.325,61.725) 32.525,61.525 C77.2@32.975,61.525
  Bottom Layer w0.3: C35.2@29.2,65.625 v1(29.725,65.625) C30.2@30.25,65.625 ; C30.2@30.5,65.625 v1(31.025,65.625) C76.2@31.55,65.625 ; C76.2@31.8,65.625 v1(32.325,65.625)
  other v3: 18.6,90.35 18.575,91.05 18.575,91.75
VDD_USB: C52.2 C71.2 U1.AA15 U1.AA17 U4.39 | length 57.9
  Top Layer w0.09: U1.AA15@33.5,58.2 33.75,58.45 34.25,58.45 ; v1@34.25,59.125 v1(34.25,59.05) 34.25,58.45 ; U1.AA17@34.5,58.2 34.25,58.45
  Top Layer w0.2: U4.39@15.8,84.275 16.85,84.275 ; C52.2@17.625,84.575 C52.2@17.775,84.725 C52.2@17.775,84.66 ; 16.85,84.275 16.95,84.375 17.775,84.375 18.059,84.375 18.175,84.375 18.117,84.317 18.075,84.275 16.85,84.275
  Top Layer w0.45: C52.2@17.775,84.66 17.775,84.659 18.059,84.375 18.117,84.317 18.409,84.025 18.625,84.025 19.075,83.575 v3(19.35,83.575)
  Signal Layer 4 w0.3: v3(19.35,83.575) 19.35,80.475 15.15,76.275 15.15,65.725 27.75,53.125 v1(32.9,53.125)
  Bottom Layer w0.3: v1(32.9,53.125) 33.155,53.38 33.63,53.38 34.25,54 v1(34.25,59.05) ; C71.2@33.625,58.275 34.225,58.275
VDDA: C49.2 C70.2 R41.1 U1.1H1 U4.20 | length 41.4
  Top Layer w0.09: U1.1H1@29.4,60.75 v1(29.725,60.425)
  Top Layer w0.2: 9.075,83.475 U4.20@9.9,83.475
  Top Layer w0.3: C49.2@7.7,82.175 8.275,82.75 8.275,82.873 8.55,83.148 8.55,83.155 8.87,83.475 9.075,83.475
  Top Layer w0.4: v3(7.55,81.6) 7.55,82.025 C49.2@7.7,82.175
  Bottom Layer w0.2: C70.2@29.35,60.05 v1(29.725,60.425)
  Bottom Layer w0.3: v3(7.55,81.6) 6.95,81 6.95,77.425 7.925,76.45 7.925,71.6 19.925,59.6 23.5,59.6 28.65,59.6 28.925,59.875 C70.2@29.125,59.875
VDDA_1V8: C66.2 C67.2 U1.AB14 U1.C14 | length 20.7
  Top Layer w0.09: C67.2@32.5,55.15 v1(32.5,55.7) 33.275,56.475 33.275,57.425 U1.AB14@33,57.7
  Top Layer w0.1: U1.C14@33,67.2 33.25,67.45 v1(33.25,69.825) C66.2@33.25,70.4
  Signal Layer 4 w0.1: v1@33.25,69.8 v1(33.25,69.825)
  Signal Layer 4 w0.15: 33.025,56.225 33.025,69.575 v1@33.25,69.8
  Signal Layer 4 w0.2: v1(32.5,55.7) 33.025,56.225
VREF+: C50.2 C58.2 R41.2 U1.R4 | length 6.5
  Top Layer w0.1: U1.R4@28,61.2 28.025,61.2 28.537,61.713 v1@28.575,61.75
  Bottom Layer w0.2: C58.2@28.3,61.175 28.3,61.5 v1(28.525,61.725)
  Bottom Layer w0.3: R41.2@23.5,60.625 23.625,60.625 24.175,61.175 C50.2@27.275,61.175 C58.2@28.3,61.175
VREF_DDR: C17.1 C84.2 C149.1 C150.1 U1.AC20 U2.H4 U2.J11 U4.16 | length 149
  Top Layer w0.12: U2.J11@50.9,62.3 51.247,62.3 51.572,61.975 52.075,61.975 v1(52.1,62) ; v1@56.1,62.625 56.1,62.247 56.367,61.98 56.37,61.98 56.5,61.85 U2.H4@56.5,61.65
  Top Layer w0.15: U1.AC20@36,57.196 36,55.6 v1(36.2,55.4)
  Top Layer w0.2: 8.575,85.075 U4.16@9.9,85.075 ; C17.1@36.2,54.825 v1(36.2,55.4)
  Top Layer w0.3: v3(7.65,84.75) C84.2@7.65,85.45 8.2,85.45 8.575,85.075
  Signal Layer 4 w0.5: 6.375,84.75 v3(7.65,84.75)
  Signal Layer 4 w0.6: 6.375,84.75 4.2,86.925 4.2,89.325 4.875,90 4.875,93.5 10.425,99.05 38.65,99.05 61.625,76.075 61.625,63.2 61.625,55.25 58.425,52.05 37.775,52.05 36.2,53.625 v1(36.2,55.4)
  Bottom Layer w0.3: C150.1@51.425,61.325 51.437,61.338 v1(52.1,62) 52.6,62 52.8,61.8 55.176,61.8 55.438,62.062 56.075,62.7 56.576,63.2 v1(61.65,63.2)
  other v1: 56.1,62.675
pads on no net: U1.A2 U1.A3 U1.A4 U1.A5 U1.A7 U1.A8 U1.A14 U1.A16 U1.A17 U1.A19 U1.A20 U1.AA1 U1.AA2 U1.AA3 U1.AA4 U1.AA6 U1.AA7 U1.AA9 U1.AA10 U1.AA11 U1.AA13 U1.AA14 U1.AA18 U1.AB1 U1.AB2 U1.AB4 U1.AB5 U1.AB6 U1.AB7 U1.AB8 U1.AB9 U1.AB10 U1.AB11 U1.AB12 U1.AB16 U1.AB17 U1.AB18 U1.AB19 U1.AC2 U1.AC3 U1.AC4 U1.AC5 U1.AC7 U1.AC8 U1.AC10 U1.AC11 U1.AC13 U1.AC14 U1.AC16 U1.AC17 U1.AC19 U1.B1 U1.B2 U1.B3 U1.B4 U1.B5 U1.B6 U1.B7 U1.B8 U1.B9 U1.B14 U1.B15 U1.B16 U1.B17 U1.B19 U1.B20 U1.C1 U1.C2 U1.C3 U1.C4 U1.C5 U1.C6 U1.C8 U1.C10 U1.C15 U1.C19 U1.C20 U1.D1 U1.D2 U1.D3 U1.D5 U1.D6 U1.D7 U1.D8 U1.D9 U1.D10 U1.D11 U1.D12 U1.D13 U1.D14 U1.D15 U1.D16 U1.D17 U1.D18 U1.D19 U1.D20 U1.E1 U1.E2 U1.E3 U1.E4 U1.F2 U1.F3 U1.F4 U1.F20 U1.G1 U1.G2 U1.G3 U1.G4 U1.H1 U1.H2 U1.H4 U1.J2 U1.J3 U1.J4 U1.K1 U1.K2 U1.K3 U1.K4 U1.K20 U1.L1 U1.L2 U1.L3 U1.L4 U1.L21 U1.L22 U1.L23 U1.M2 U1.M4 U1.M20 U1.M21 U1.N1 U1.N2 U1.N3 U1.N4 U1.N20 U1.N21 U1.P1 U1.P2 U1.P4 U1.P20 U1.P23 U1.R3 U1.R20 U1.R21 U1.R22 U1.T1 U1.T2 U1.T3 U1.T4 U1.U1 U1.U2 U1.U3 U1.U4 U1.U20 U1.V2 U1.V3 U1.V4 U1.W1 U1.W2 U1.W4 U1.Y1 U1.Y2 U1.Y3 U1.Y4 U1.Y5 U1.Y6 U1.Y7 U1.Y8 U1.Y9 U1.Y10 U1.Y11 U1.Y12 U1.Y13 U1.Y14 U1.Y15 U1.Y16 U1.Y17 U1.Y19 U2.A1 U2.A2 U2.A12 U2.A13 U2.B1 U2.B4 U2.B13 U2.C4 U2.K4 U2.K9 U2.L4 U2.R3 U2.T1 U2.T13 U2.U1 U2.U2 U2.U12 U2.U13 U4.2 U4.18 U4.21 U4.23 U4.34 U4.35 U4.38 U5.A1 U5.A2 U5.A7 U5.A8 U5.A9 U5.A10 U5.A11 U5.A12 U5.A13 U5.A14 U5.B1 U5.B7 U5.B8 U5.B9 U5.B10 U5.B11 U5.B12 U5.B13 U5.B14 U5.C1 U5.C3 U5.C5 U5.C7 U5.C8 U5.C9 U5.C10 U5.C11 U5.C12 U5.C13 U5.C14 U5.D1 U5.D2 U5.D3 U5.D4 U5.D12 U5.D13 U5.D14 U5.E1 U5.E2 U5.E3 U5.E5 U5.E8 U5.E9 U5.E10 U5.E12 U5.E13 U5.E14 U5.F1 U5.F2 U5.F3 U5.F10 U5.F12 U5.F13 U5.F14 U5.G1 U5.G2 U5.G3 U5.G10 U5.G12 U5.G13 U5.G14 U5.H1 U5.H2 U5.H3 U5.H5 U5.H12 U5.H13 U5.H14 U5.J1 U5.J2 U5.J3 U5.J12 U5.J13 U5.J14 U5.K1 U5.K2 U5.K3 U5.K6 U5.K7 U5.K10 U5.K12 U5.K13 U5.K14 U5.L1 U5.L2 U5.L3 U5.L12 U5.L13 U5.L14 U5.M1 U5.M2 U5.M3 U5.M7 U5.M8 U5.M9 U5.M10 U5.M11 U5.M12 U5.M13 U5.M14 U5.N1 U5.N3 U5.N6 U5.N7 U5.N8 U5.N9 U5.N10 U5.N11 U5.N12 U5.N13 U5.N14 U5.P1 U5.P2 U5.P7 U5.P8 U5.P9 U5.P10 U5.P11 U5.P12 U5.P13 U5.P14

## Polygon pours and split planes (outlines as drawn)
GND on Top Layer "Top Layer-No Net" (solid, remove dead copper, pour order 232): 0,120.25 89,120.25 89,0 0,0
NetL1_1 on Top Layer "NO TR" (solid, remove dead copper, pour order 114): 12.75,87.1 12.75,87.575 13.3,88.125 14.05,88.125 14.325,88.4 14.325,90.35 14.15,90.525 13.25,90.525 13.1,90.375 13.1,88.975 12.55,88.425 12.55,87.1
VDD2_DDR on Top Layer "NO TR" (solid, remove dead copper, pour order 154): 11.3,91.3 10.85,91.75 8.2,91.75 7.975,91.525 7.975,90.125 8.075,90.025 9.525,90.025 10.8,90.025 11.3,90.525
NetL2_1 on Top Layer "NO TR" (solid, remove dead copper, pour order 156): 9.95,88.45 9.225,88.45 9.1,88.575 9.1,89.35 9.2,89.45 11.175,89.45 11.325,89.3 11.325,87.8 11.15,87.45 11.15,87.375 10.95,87.375 10.95,87.45
VDD1_DDR on Top Layer "NO TR" (solid, remove dead copper, pour order 158): 9.7,85.775 7.875,85.775 7.7,85.95 7.7,86.7 7.875,86.875 8.65,86.875 9.075,86.45 9.55,85.975 9.7,85.975
VDD on Top Layer "NO TR" (solid, pour order 160): 10.3,86.45 10.3,86.175 9.475,86.175 8.525,87.125 7.95,87.125 7.9,87.175 7.9,88.075 7.975,88.15 8.6,88.15
NetL3_1 on Top Layer "NO TR" (solid, remove dead copper, pour order 164): 12.925,81.575 12.95,81.6 13.15,81.6 13.175,81.575 13.175,81.425 13.375,81.225 13.775,81.225 14.4,80.6 16.575,80.6 16.625,80.55 16.625,79.225 16.575,79.175 15.125,79.175 14.575,79.175 14.525,79.225 14.525,79.75 12.925,81.35
5V_VIN on Top Layer "NO TR" (solid, remove dead copper, pour order 166): 14.425,78.575 14.325,78.475 13.075,78.475 13,78.55 13,80.075 12.525,80.55 12.525,81.575 12.55,81.6 12.75,81.6 12.775,81.575 12.775,81.293 14.425,79.656
5V_VIN on Top Layer "NO TR" (solid, remove dead copper, pour order 168): 10.925,81.575 10.95,81.6 11.15,81.6 11.175,81.575 11.175,80.725 10.5,80.05 10.5,78.475 7.95,78.475 7.775,78.65 7.775,79.025 7.9,79.15 8.825,79.15 9.175,79.5 9.438,79.75 9.701,79.75 9.75,79.801 9.75,80.338 10.925,81.451
NetL4_1 on Top Layer "NO TR" (solid, remove dead copper, pour order 170): 11.325,81.575 11.35,81.6 11.55,81.6 11.575,81.575 11.575,81.3 12.725,80.153 12.725,79.225 12.675,79.175 10.675,79.175 10.625,79.225 10.625,79.975 11.325,80.675
VDD on Top Layer "NO TR" (solid, remove dead copper, pour order 172): 14.55,78.1 17.25,78.1 17.875,77.475 17.875,74.35 17.525,74 16.6,74 16.1,74.5 16.1,75.95 14.55,75.95
VDD_CORE on Top Layer "NO TR" (solid, remove dead copper, pour order 174): 17.5,89.95 17.5,91.564 18.063,92.127 18.748,92.127 19.05,91.825 19.05,89.925 18.9,89.775 17.675,89.775
3V3 on Top Layer "NO TR" (solid, remove dead copper, pour order 178): 11.75,74.55 12.725,75.525 12.725,78.15 10.625,78.15 10.625,75.9 10.45,75.725 9.725,75.725 9.725,74.675 9.85,74.55
5V_VIN on Top Layer "NO TR" (solid, remove dead copper, pour order 180): 12.35,88.125 12.35,88.4 13.025,89.075 13.025,90.125 12.925,90.225 11.675,90.225 11.5,90.05 11.5,89.1 12.15,88.45 12.15,88.125
5V_VIN on Top Layer "NO TR" (solid, pour order 162): 8.675,89.05 7.588,89.05 6.475,89.95 6.475,90.15 5.7,90.15 5.7,88.425 5.85,88.275 8.6,88.275 10.35,86.525 10.75,86.525 10.75,87.45 9.875,88.325 9.35,88.325
VDD_CORE on Signal Layer 4 "VDD_CORE" (solid, remove dead copper, pour order 220): 26.225,84.05 20.775,89.5 18.1,89.5 18.1,92.3 26.475,92.3 29.375,89.4 32.725,86.048 32.725,61.409 31.65,61.409 31.65,62.025 31.156,62.5 26.225,62.5
VDD on Signal Layer 4 "VDD" (solid, remove dead copper, pour order 222): 16.126,74.8 16.126,74.751 16.126,74.625 16.126,71.05 23.625,59.475 32.75,59.475 32.75,60.841 31.114,62.375 25.907,62.375 18.355,75.025 16.274,75.025 16.126,74.9
5V_VIN on Signal Layer 4 "5V_VIN" (solid, remove dead copper, pour order 224): 17.65,85.3 17.65,84.775 19.3,84.775 19.3,79.825 17.875,78.4 4.4,78.4 4.4,90.15 7.9,90.15 7.9,87.375 11.325,87.375 11.325,90.15 16.325,90.15 16.325,85.3
VDD2_DDR on Signal Layer 4 "VDD2_DDR" (solid, remove dead copper, pour order 218): 33.2,90.475 31.025,92.65 13.15,92.65 10.3,89.8 8.125,89.8 8.125,91.775 11.85,95.5 28.475,95.5 33.825,95.5 38.75,90.575 38.75,73.541 51.891,73.541 56.75,70.4 60.25,68.225 60.25,52.475 37.625,52.475 34.725,56.375 33.2,58.45
GND on Signal Layer 4 "GND" (solid, pour order 230): 0,120 89,120 89,0 0,0
GND on Signal Layer 1 "GND" (solid, remove dead copper, pour order 104): 0.408,119.592 89,119.592 89,0.408 0.408,0.408
GND on Bottom Layer "GND" (solid, pour order 228): 0,120 89,120 89,0 0,0
GND on Signal Layer 3 "gnd" (solid, pour order 234): 0.05,119.95 88.95,119.95 88.95,0.05 0.05,0.05 0.05,119.95
GND on Signal Layer 2 "gnd" (solid, pour order 236): 0.05,119.95 88.95,119.95 88.95,0.05 0.05,0.05 0.05,119.95

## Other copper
Top Layer:
  pour cut-out: 26.5,57.088 26.5,68.169 35.663,68.264 35.663,69.305 40.933,74.575 48.858,74.575 55.383,68.05 58.708,68.05 61.258,65.5 61.258,57.455 58.803,55 55.736,55 55.058,54.225 55.058,52.325 52.883,50.15 39.65,50.15 35.15,54.65 35.15,57.088
Signal Layer 2:
  pour cut-out: 37.224,69.1 55.375,69.1 55.375,52.525 54.625,52.525 46.125,52.525 37.224,61.426
Bottom Layer:
  pour cut-out: 34.5,67.5 35.75,68.75 55.25,68.75 58,68.75 59,67.75 59,64 60.25,62.75 60.25,58 60.25,59.3 58.55,58 57.775,58 52.266,52.491 51.242,52.491 47.692,55.05 43.8,55.05 39.025,55.05 34.5,59.575

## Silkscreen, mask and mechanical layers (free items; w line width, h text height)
Bottom Overlay:
  lines w0.15: 28.5,53.25 29.75,57.75 ; 29,57.25 29.75,57.75 ; 30,57 29.75,57.75 ; 15.5,37 29.5,37 29.5,53.25 15.75,53.25 15.5,53.25 15.5,37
